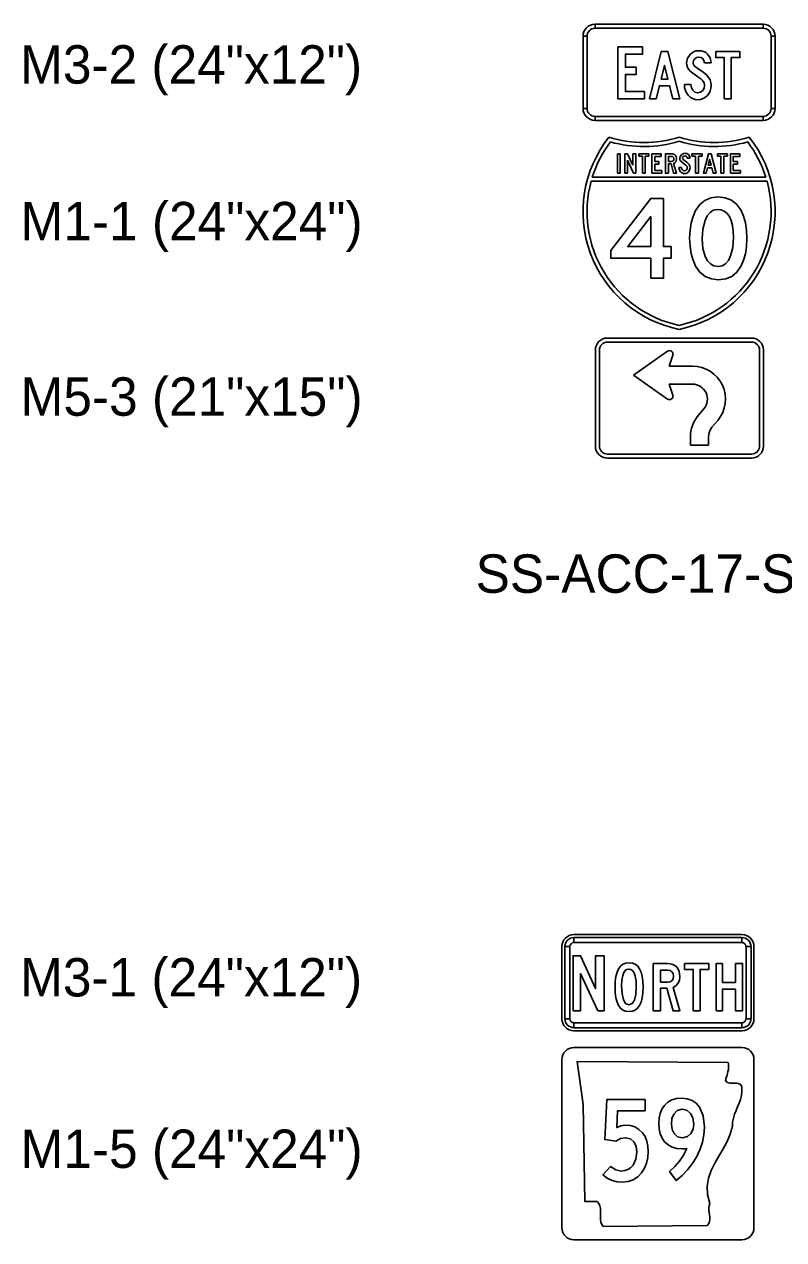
# Model space of a CAD drawing. Extents: x 620856.8 to 620948.6, y 415598.8 to 415658.2.
# Drawn here: x 620857.63 to 620865.53, y 415643.04 to 415655.69 of the extents above; entities that cross this region are included whole.
import ezdxf

# ---------------------------------------------------------------- set-up
doc = ezdxf.new("R2010")
doc.units = 0
doc.layers.add('SIGNS', color=7, linetype='Continuous')

msp = doc.modelspace()

# ---------------------------------------------------------------- linework, layer by layer
at = {"layer": 'SIGNS'}
for p, q in [((620863.57, 415655.647), (620863.57, 415655.689)), ((620865.32, 415655.689), (620865.32, 415655.647)), ((620863.445, 415655.564), (620863.487, 415655.564)), ((620865.403, 415655.564), (620865.445, 415655.564)), ((620863.487, 415654.814), (620863.445, 415654.814)), ((620865.445, 415654.814), (620865.403, 415654.814)), ((620863.57, 415654.689), (620863.57, 415654.73)), ((620865.32, 415654.73), (620865.32, 415654.689)), ((620863.833, 415654.342), (620863.804, 415654.342)), ((620863.804, 415654.342), (620863.804, 415654.138)), ((620863.833, 415654.138), (620863.833, 415654.342)), ((620863.907, 415654.342), (620863.879, 415654.342)), ((620863.879, 415654.342), (620863.879, 415654.138)), ((620863.964, 415654.221), (620863.907, 415654.342)), ((620863.907, 415654.138), (620863.907, 415654.276)), ((620863.907, 415654.276), (620863.972, 415654.138)), ((620863.995, 415654.342), (620863.964, 415654.342)), ((620863.964, 415654.342), (620863.964, 415654.221)), ((620863.995, 415654.138), (620863.995, 415654.342)), ((620864.13, 415654.342), (620864.025, 415654.342)), ((620864.025, 415654.342), (620864.025, 415654.317)), ((620864.025, 415654.317), (620864.063, 415654.317)), ((620864.063, 415654.317), (620864.063, 415654.138)), ((620864.092, 415654.138), (620864.092, 415654.317)), ((620864.092, 415654.317), (620864.13, 415654.317)), ((620864.13, 415654.317), (620864.13, 415654.342)), ((620864.258, 415654.342), (620864.161, 415654.342)), ((620864.161, 415654.342), (620864.161, 415654.138)), ((620864.191, 415654.262), (620864.191, 415654.314)), ((620864.191, 415654.314), (620864.258, 415654.314)), ((620864.258, 415654.314), (620864.258, 415654.342)), ((620864.457, 415654.313), (620864.453, 415654.294)), ((620864.453, 415654.294), (620864.454, 415654.283)), ((620864.454, 415654.283), (620864.457, 415654.274)), ((620864.469, 415654.331), (620864.457, 415654.313)), ((620864.457, 415654.274), (620864.462, 415654.265)), ((620864.477, 415654.338), (620864.469, 415654.331)), ((620864.486, 415654.342), (620864.477, 415654.338)), ((620864.482, 415654.294), (620864.484, 415654.304)), ((620864.483, 415654.288), (620864.482, 415654.294)), ((620864.486, 415654.282), (620864.483, 415654.288)), ((620864.484, 415654.304), (620864.489, 415654.311)), ((620864.495, 415654.345), (620864.486, 415654.342)), ((620864.502, 415654.27), (620864.486, 415654.282)), ((620864.489, 415654.311), (620864.497, 415654.316)), ((620864.506, 415654.346), (620864.495, 415654.345)), ((620864.497, 415654.316), (620864.506, 415654.318)), ((620864.526, 415654.254), (620864.502, 415654.27)), ((620864.517, 415654.345), (620864.506, 415654.346)), ((620864.506, 415654.318), (620864.517, 415654.316)), ((620864.527, 415654.343), (620864.517, 415654.345)), ((620864.517, 415654.316), (620864.524, 415654.312)), ((620864.524, 415654.312), (620864.528, 415654.305)), ((620864.536, 415654.338), (620864.527, 415654.343)), ((620864.528, 415654.305), (620864.531, 415654.294)), ((620864.531, 415654.294), (620864.559, 415654.294)), ((620864.544, 415654.332), (620864.536, 415654.338)), ((620864.555, 415654.315), (620864.544, 415654.332)), ((620864.559, 415654.294), (620864.555, 415654.315)), ((620864.685, 415654.342), (620864.579, 415654.342)), ((620864.579, 415654.342), (620864.579, 415654.317)), ((620864.579, 415654.317), (620864.617, 415654.317)), ((620864.617, 415654.317), (620864.617, 415654.138)), ((620864.646, 415654.138), (620864.646, 415654.317)), ((620864.646, 415654.317), (620864.685, 415654.317)), ((620864.685, 415654.317), (620864.685, 415654.342)), ((620864.949, 415654.342), (620864.844, 415654.342)), ((620864.844, 415654.342), (620864.844, 415654.317)), ((620864.844, 415654.317), (620864.881, 415654.317)), ((620864.881, 415654.317), (620864.881, 415654.138)), ((620864.911, 415654.138), (620864.911, 415654.317)), ((620864.911, 415654.317), (620864.949, 415654.317)), ((620864.949, 415654.317), (620864.949, 415654.342)), ((620865.077, 415654.342), (620864.979, 415654.342)), ((620864.979, 415654.342), (620864.979, 415654.138)), ((620865.009, 415654.262), (620865.009, 415654.314)), ((620865.009, 415654.314), (620865.077, 415654.314)), ((620865.077, 415654.314), (620865.077, 415654.342)), ((620864.233, 415654.262), (620864.191, 415654.262)), ((620864.191, 415654.166), (620864.191, 415654.234)), ((620864.191, 415654.234), (620864.233, 415654.234)), ((620864.266, 415654.166), (620864.191, 415654.166)), ((620864.233, 415654.234), (620864.233, 415654.262)), ((620864.266, 415654.138), (620864.266, 415654.166)), ((620864.472, 415654.199), (620864.444, 415654.199)), ((620864.444, 415654.199), (620864.444, 415654.198)), ((620864.444, 415654.198), (620864.445, 415654.185)), ((620864.445, 415654.185), (620864.448, 415654.174)), ((620864.448, 415654.174), (620864.453, 415654.163)), ((620864.453, 415654.163), (620864.46, 415654.153)), ((620864.46, 415654.153), (620864.469, 415654.145)), ((620864.462, 415654.265), (620864.469, 415654.257)), ((620864.469, 415654.257), (620864.502, 415654.234)), ((620864.469, 415654.145), (620864.479, 415654.139)), ((620864.474, 415654.186), (620864.472, 415654.199)), ((620864.48, 415654.175), (620864.474, 415654.186)), ((620864.489, 415654.167), (620864.48, 415654.175)), ((620864.502, 415654.164), (620864.489, 415654.167)), ((620864.502, 415654.234), (620864.514, 415654.224)), ((620864.514, 415654.166), (620864.502, 415654.164)), ((620864.514, 415654.224), (620864.522, 415654.217)), ((620864.523, 415654.174), (620864.514, 415654.166)), ((620864.522, 415654.217), (620864.529, 415654.207)), ((620864.529, 415654.184), (620864.523, 415654.174)), ((620864.525, 415654.139), (620864.535, 415654.145)), ((620864.541, 415654.24), (620864.526, 415654.254)), ((620864.529, 415654.207), (620864.531, 415654.196)), ((620864.531, 415654.196), (620864.529, 415654.184)), ((620864.535, 415654.145), (620864.544, 415654.153)), ((620864.549, 415654.23), (620864.541, 415654.24)), ((620864.544, 415654.153), (620864.551, 415654.162)), ((620864.555, 415654.22), (620864.549, 415654.23)), ((620864.551, 415654.162), (620864.555, 415654.173)), ((620864.558, 415654.208), (620864.555, 415654.22)), ((620864.555, 415654.173), (620864.558, 415654.184)), ((620864.559, 415654.196), (620864.558, 415654.208)), ((620864.558, 415654.184), (620864.559, 415654.196)), ((620865.052, 415654.262), (620865.009, 415654.262)), ((620865.009, 415654.166), (620865.009, 415654.234)), ((620865.009, 415654.234), (620865.052, 415654.234)), ((620865.085, 415654.166), (620865.009, 415654.166)), ((620865.052, 415654.234), (620865.052, 415654.262)), ((620865.085, 415654.138), (620865.085, 415654.166)), ((620865.349, 415654.096), (620863.541, 415654.096)), ((620863.804, 415654.138), (620863.833, 415654.138)), ((620863.879, 415654.138), (620863.907, 415654.138)), ((620863.972, 415654.138), (620863.995, 415654.138)), ((620864.063, 415654.138), (620864.092, 415654.138)), ((620864.161, 415654.138), (620864.266, 415654.138)), ((620864.479, 415654.139), (620864.49, 415654.135)), ((620864.49, 415654.135), (620864.502, 415654.134)), ((620864.502, 415654.134), (620864.514, 415654.135)), ((620864.514, 415654.135), (620864.525, 415654.139)), ((620864.617, 415654.138), (620864.646, 415654.138)), ((620864.881, 415654.138), (620864.911, 415654.138)), ((620864.979, 415654.138), (620865.085, 415654.138)), ((620863.699, 415652.423), (620865.199, 415652.423)), ((620865.199, 415652.381), (620863.699, 415652.381)), ((620865.199, 415652.423), (620865.199, 415652.423)), ((620863.574, 415651.298), (620863.574, 415652.298)), ((620863.616, 415652.298), (620863.616, 415651.298)), ((620864.325, 415652.287), (620863.97, 415652.037)), ((620864.342, 415652.131), (620864.379, 415652.245)), ((620865.282, 415651.298), (620865.282, 415652.298)), ((620865.324, 415652.298), (620865.324, 415651.298)), ((620864.584, 415652.131), (620864.342, 415652.131)), ((620863.97, 415652.037), (620864.325, 415651.788)), ((620864.379, 415651.83), (620864.342, 415651.944)), ((620864.342, 415651.944), (620864.584, 415651.944)), ((620864.704, 415651.687), (620864.644, 415651.615)), ((620864.787, 415651.494), (620864.848, 415651.566)), ((620864.563, 415651.394), (620864.563, 415651.308)), ((620864.751, 415651.308), (620864.751, 415651.394)), ((620864.563, 415651.308), (620864.751, 415651.308)), ((620863.699, 415651.214), (620865.199, 415651.214)), ((620865.199, 415651.173), (620863.699, 415651.173)), ((620863.699, 415651.173), (620863.699, 415651.173)), ((620865.1, 415646.213), (620863.35, 415646.213)), ((620863.35, 415646.13), (620863.35, 415646.182)), ((620865.1, 415646.182), (620865.1, 415646.13)), ((620863.225, 415646.088), (620863.225, 415645.338)), ((620863.256, 415646.088), (620863.309, 415646.088)), ((620865.142, 415646.088), (620865.194, 415646.088)), ((620865.225, 415645.338), (620865.225, 415646.088)), ((620863.309, 415645.338), (620863.256, 415645.338)), ((620863.35, 415645.244), (620863.35, 415645.296)), ((620865.1, 415645.296), (620865.1, 415645.244)), ((620865.194, 415645.338), (620865.142, 415645.338)), ((620863.35, 415645.213), (620865.1, 415645.213)), ((620865.1, 415645.037), (620863.35, 415645.037)), ((620863.225, 415644.912), (620863.225, 415643.162)), ((620865.225, 415643.162), (620865.225, 415644.912)), ((620863.225, 415643.162), (620863.225, 415643.162)), ((620863.35, 415643.037), (620865.1, 415643.037))]:
    msp.add_line(p, q, dxfattribs=at)
for points in [[(620865.32, 415655.689), (620863.57, 415655.689), (620863.57, 415655.647), (620865.32, 415655.647), (620865.32, 415655.689), (620865.32, 415655.689)], [(620863.445, 415655.564), (620863.445, 415654.814), (620863.487, 415654.814), (620863.487, 415655.564), (620863.445, 415655.564), (620863.445, 415655.564)], [(620865.445, 415654.814), (620865.445, 415655.564), (620865.403, 415655.564), (620865.403, 415654.814), (620865.445, 415654.814), (620865.445, 415654.814)], [(620864.086, 415654.988), (620863.887, 415654.988), (620863.887, 415655.167), (620864, 415655.167), (620864, 415655.242), (620863.887, 415655.242), (620863.887, 415655.379), (620864.065, 415655.379), (620864.065, 415655.453), (620863.809, 415655.453), (620863.809, 415654.914), (620864.086, 415654.914)], [(620864.501, 415655.061), (620864.501, 415655.057), (620864.503, 415655.027), (620864.511, 415654.999), (620864.523, 415654.974), (620864.539, 415654.951), (620864.561, 415654.93), (620864.585, 415654.916), (620864.611, 415654.907), (620864.64, 415654.904), (620864.669, 415654.907), (620864.696, 415654.915), (620864.72, 415654.929), (620864.741, 415654.949), (620864.757, 415654.972), (620864.769, 415654.997), (620864.776, 415655.024), (620864.778, 415655.054), (620864.775, 415655.082), (620864.767, 415655.109), (620864.753, 415655.135), (620864.734, 415655.159), (620864.697, 415655.191), (620864.64, 415655.23), (620864.603, 415655.258), (620864.595, 415655.272), (620864.592, 415655.289), (620864.596, 415655.311), (620864.609, 415655.329), (620864.628, 415655.342), (620864.651, 415655.346), (620864.675, 415655.342), (620864.693, 415655.33), (620864.703, 415655.313), (620864.71, 415655.289), (620864.778, 415655.289), (620864.767, 415655.339), (620864.741, 415655.378), (620864.722, 415655.394), (620864.701, 415655.405), (620864.676, 415655.411), (620864.649, 415655.414), (620864.624, 415655.411), (620864.601, 415655.404), (620864.58, 415655.392), (620864.561, 415655.376), (620864.533, 415655.335), (620864.524, 415655.287), (620864.526, 415655.262), (620864.533, 415655.24), (620864.545, 415655.219), (620864.561, 415655.2), (620864.641, 415655.143), (620864.67, 415655.12), (620864.689, 415655.104), (620864.705, 415655.079), (620864.71, 415655.053), (620864.706, 415655.024), (620864.692, 415654.999), (620864.669, 415654.981), (620864.64, 415654.975), (620864.61, 415654.982), (620864.587, 415655.002), (620864.573, 415655.029), (620864.569, 415655.061)], [(620864.916, 415654.914), (620864.987, 415654.914), (620864.987, 415655.342), (620865.079, 415655.342), (620865.079, 415655.404), (620864.826, 415655.404), (620864.826, 415655.342), (620864.916, 415655.342)], [(620863.57, 415654.689), (620865.32, 415654.689), (620865.32, 415654.73), (620863.57, 415654.73), (620863.57, 415654.689), (620863.57, 415654.689)], [(620865.1, 415646.182), (620863.35, 415646.182), (620863.35, 415646.13), (620865.1, 415646.13), (620865.1, 415646.182), (620865.1, 415646.182)], [(620863.256, 415646.088), (620863.256, 415645.338), (620863.309, 415645.338), (620863.309, 415646.088), (620863.256, 415646.088), (620863.256, 415646.088)], [(620865.194, 415645.338), (620865.194, 415646.088), (620865.142, 415646.088), (620865.142, 415645.338), (620865.194, 415645.338), (620865.194, 415645.338)], [(620863.341, 415645.421), (620863.419, 415645.421), (620863.419, 415645.808), (620863.6, 415645.421), (620863.664, 415645.421), (620863.664, 415645.993), (620863.576, 415645.993), (620863.576, 415645.652), (620863.419, 415645.993), (620863.341, 415645.993)], [(620864.592, 415645.421), (620864.664, 415645.421), (620864.664, 415645.85), (620864.755, 415645.85), (620864.755, 415645.912), (620864.503, 415645.912), (620864.503, 415645.85), (620864.592, 415645.85)], [(620864.83, 415645.421), (620864.897, 415645.421), (620864.897, 415645.646), (620865.032, 415645.646), (620865.032, 415645.421), (620865.107, 415645.421), (620865.107, 415645.912), (620865.032, 415645.912), (620865.032, 415645.715), (620864.897, 415645.715), (620864.897, 415645.912), (620864.83, 415645.912)], [(620863.35, 415645.244), (620865.1, 415645.244), (620865.1, 415645.296), (620863.35, 415645.296), (620863.35, 415645.244), (620863.35, 415645.244)], [(620864.955, 415644.883), (620864.96, 415644.864), (620864.961, 415644.844), (620864.961, 415644.825), (620864.958, 415644.806), (620864.954, 415644.787), (620864.95, 415644.768), (620864.944, 415644.749), (620864.938, 415644.731), (620864.933, 415644.713), (620864.928, 415644.694), (620864.942, 415644.678), (620864.959, 415644.669), (620864.979, 415644.665), (620865.001, 415644.665), (620865.022, 415644.665), (620865.043, 415644.666), (620865.062, 415644.663), (620865.078, 415644.657), (620865.091, 415644.645), (620865.099, 415644.625), (620865.1, 415644.579), (620865.094, 415644.537), (620865.084, 415644.496), (620865.069, 415644.458), (620865.054, 415644.42), (620865.038, 415644.382), (620865.023, 415644.343), (620865.011, 415644.304), (620865.002, 415644.262), (620865, 415644.218), (620864.978, 415644.136), (620864.944, 415644.058), (620864.904, 415643.982), (620864.86, 415643.907), (620864.816, 415643.833), (620864.779, 415643.757), (620864.751, 415643.678), (620864.736, 415643.596), (620864.74, 415643.508), (620864.765, 415643.415), (620864.758, 415643.391), (620864.755, 415643.368), (620864.756, 415643.344), (620864.759, 415643.319), (620864.762, 415643.296), (620864.765, 415643.272), (620864.765, 415643.249), (620864.762, 415643.227), (620864.754, 415643.206), (620864.738, 415643.186), (620863.655, 415643.176), (620863.64, 415643.196), (620863.631, 415643.22), (620863.628, 415643.246), (620863.627, 415643.275), (620863.628, 415643.304), (620863.628, 415643.334), (620863.626, 415643.363), (620863.621, 415643.39), (620863.61, 415643.414), (620863.591, 415643.434), (620863.465, 415643.434), (620863.447, 415644.446), (620863.383, 415644.893), (620864.955, 415644.883), (620864.955, 415644.883)], [(620863.65, 415643.711), (620863.698, 415643.678), (620863.748, 415643.655), (620863.8, 415643.641), (620863.855, 415643.637), (620863.914, 415643.643), (620863.967, 415643.661), (620864.014, 415643.691), (620864.055, 415643.734), (620864.086, 415643.782), (620864.107, 415643.834), (620864.121, 415643.892), (620864.125, 415643.955), (620864.121, 415644.012), (620864.11, 415644.064), (620864.091, 415644.111), (620864.063, 415644.151), (620864.027, 415644.186), (620863.984, 415644.211), (620863.935, 415644.226), (620863.881, 415644.231), (620863.84, 415644.224), (620863.796, 415644.204), (620863.805, 415644.379), (620864.092, 415644.379), (620864.092, 415644.495), (620863.692, 415644.495), (620863.671, 415644.079), (620863.788, 415644.064), (620863.836, 415644.09), (620863.889, 415644.099), (620863.941, 415644.087), (620863.979, 415644.052), (620863.999, 415644.006), (620864.006, 415643.949), (620863.996, 415643.874), (620863.966, 415643.813), (620863.941, 415643.786), (620863.913, 415643.767), (620863.879, 415643.756), (620863.842, 415643.752), (620863.785, 415643.764), (620863.731, 415643.799)]]:
    msp.add_lwpolyline(points, close=True, dxfattribs=at)
for points in [[(620864.136, 415654.914), (620864.208, 415654.914), (620864.241, 415655.049), (620864.347, 415655.049), (620864.381, 415654.914), (620864.453, 415654.914), (620864.329, 415655.404), (620864.26, 415655.404), (620864.136, 415654.914)], [(620864.258, 415655.118), (620864.293, 415655.261), (620864.329, 415655.118), (620864.258, 415655.118)], [(620863.714, 415654.513), (620863.714, 415654.513)], [(620863.73, 415654.465), (620863.73, 415654.465)], [(620864.445, 415654.471), (620864.445, 415654.471)], [(620865.16, 415654.465), (620865.16, 415654.465)], [(620865.176, 415654.513), (620865.176, 415654.513)], [(620864.334, 415654.138), (620864.334, 415654.235), (620864.362, 415654.235), (620864.388, 415654.138), (620864.418, 415654.138), (620864.388, 415654.239), (620864.401, 415654.246), (620864.41, 415654.257), (620864.416, 415654.27), (620864.418, 415654.285), (620864.417, 415654.297), (620864.414, 415654.308), (620864.41, 415654.318), (620864.404, 415654.326), (620864.396, 415654.333), (620864.387, 415654.338), (620864.376, 415654.341), (620864.363, 415654.342), (620864.302, 415654.342), (620864.302, 415654.138), (620864.334, 415654.138)], [(620864.334, 415654.262), (620864.334, 415654.314), (620864.364, 415654.314), (620864.375, 415654.313), (620864.383, 415654.307), (620864.389, 415654.299), (620864.39, 415654.288), (620864.389, 415654.277), (620864.384, 415654.269), (620864.376, 415654.264), (620864.365, 415654.262), (620864.334, 415654.262)], [(620864.728, 415654.138), (620864.742, 415654.194), (620864.786, 415654.194), (620864.8, 415654.138), (620864.83, 415654.138), (620864.779, 415654.342), (620864.75, 415654.342), (620864.698, 415654.138), (620864.728, 415654.138)], [(620864.749, 415654.223), (620864.763, 415654.283), (620864.779, 415654.223), (620864.749, 415654.223)], [(620863.529, 415654.055), (620864.072, 415654.055), (620864.599, 415654.055), (620865.361, 415654.055)], [(620864.849, 415653.892), (620864.776, 415653.883), (620864.714, 415653.856), (620864.661, 415653.812), (620864.617, 415653.75), (620864.59, 415653.689), (620864.571, 415653.621), (620864.559, 415653.546), (620864.555, 415653.464), (620864.559, 415653.379), (620864.571, 415653.301), (620864.59, 415653.232), (620864.617, 415653.171), (620864.661, 415653.109), (620864.716, 415653.064), (620864.781, 415653.038), (620864.856, 415653.029), (620864.931, 415653.038), (620864.994, 415653.065), (620865.048, 415653.11), (620865.091, 415653.173), (620865.117, 415653.232), (620865.135, 415653.3), (620865.146, 415653.376), (620865.15, 415653.459), (620865.146, 415653.546), (620865.135, 415653.623), (620865.116, 415653.692), (620865.09, 415653.751), (620865.046, 415653.813), (620864.992, 415653.857), (620864.926, 415653.883), (620864.849, 415653.892)], [(620864.15, 415653.045), (620864.282, 415653.045), (620864.282, 415653.254), (620864.362, 415653.254), (620864.362, 415653.375), (620864.282, 415653.375), (620864.282, 415653.876), (620864.15, 415653.876), (620863.734, 415653.333), (620863.734, 415653.254), (620864.15, 415653.254), (620864.15, 415653.045)], [(620865.011, 415653.468), (620865.004, 415653.365), (620864.982, 415653.279), (620864.959, 415653.23), (620864.929, 415653.195), (620864.893, 415653.175), (620864.851, 415653.168), (620864.808, 415653.174), (620864.772, 415653.194), (620864.741, 415653.226), (620864.717, 415653.271), (620864.693, 415653.356), (620864.685, 415653.456), (620864.693, 415653.556), (620864.715, 415653.645), (620864.738, 415653.695), (620864.767, 415653.731), (620864.801, 415653.753), (620864.842, 415653.76), (620864.881, 415653.756), (620864.916, 415653.742), (620864.945, 415653.719), (620864.969, 415653.687), (620864.987, 415653.646), (620865, 415653.596), (620865.008, 415653.536), (620865.011, 415653.468)], [(620864.15, 415653.375), (620863.91, 415653.375), (620864.15, 415653.688), (620864.15, 415653.375)], [(620864.445, 415652.555), (620864.445, 415652.555)], [(620864.445, 415652.513), (620864.445, 415652.513)], [(620863.699, 415652.423), (620863.699, 415652.423)], [(620863.574, 415652.298), (620863.574, 415652.298)], [(620865.324, 415651.298), (620865.324, 415651.298)], [(620865.199, 415651.173), (620865.199, 415651.173)], [(620864.07, 415645.667), (620864.068, 415645.727), (620864.061, 415645.778), (620864.05, 415645.822), (620864.034, 415645.858), (620864.014, 415645.885), (620863.989, 415645.905), (620863.959, 415645.917), (620863.926, 415645.921), (620863.891, 415645.917), (620863.861, 415645.905), (620863.836, 415645.885), (620863.815, 415645.858), (620863.799, 415645.822), (620863.788, 415645.778), (620863.781, 415645.727), (620863.779, 415645.667), (620863.781, 415645.607), (620863.788, 415645.555), (620863.799, 415645.511), (620863.815, 415645.476), (620863.835, 415645.447), (620863.86, 415645.428), (620863.889, 415645.416), (620863.923, 415645.412), (620863.957, 415645.416), (620863.987, 415645.428), (620864.013, 415645.447), (620864.033, 415645.476), (620864.05, 415645.511), (620864.061, 415645.555), (620864.068, 415645.607), (620864.07, 415645.667)], [(620864, 415645.67), (620863.995, 415645.588), (620863.981, 415645.53), (620863.957, 415645.495), (620863.923, 415645.483), (620863.889, 415645.495), (620863.865, 415645.533), (620863.851, 415645.595), (620863.846, 415645.682), (620863.849, 415645.74), (620863.858, 415645.788), (620863.869, 415645.817), (620863.884, 415645.839), (620863.902, 415645.851), (620863.923, 415645.855), (620863.944, 415645.851), (620863.962, 415645.837), (620863.977, 415645.814), (620863.988, 415645.781), (620863.997, 415645.73), (620864, 415645.67)], [(620864.177, 415645.421), (620864.253, 415645.421), (620864.253, 415645.655), (620864.319, 415645.655), (620864.383, 415645.421), (620864.453, 415645.421), (620864.382, 415645.663), (620864.413, 415645.68), (620864.436, 415645.707), (620864.449, 415645.739), (620864.453, 415645.774), (620864.451, 415645.804), (620864.445, 415645.83), (620864.435, 415645.853), (620864.42, 415645.873), (620864.401, 415645.89), (620864.379, 415645.902), (620864.353, 415645.909), (620864.323, 415645.912), (620864.177, 415645.912), (620864.177, 415645.421)], [(620864.253, 415645.719), (620864.253, 415645.844), (620864.325, 415645.844), (620864.351, 415645.84), (620864.371, 415645.827), (620864.384, 415645.807), (620864.388, 415645.782), (620864.384, 415645.754), (620864.373, 415645.735), (620864.354, 415645.723), (620864.328, 415645.719), (620864.253, 415645.719)], [(620863.35, 415645.037), (620863.35, 415645.037)], [(620865.1, 415645.037), (620865.1, 415645.037)], [(620863.225, 415644.912), (620863.225, 415644.912)], [(620864.346, 415643.748), (620864.414, 415643.653), (620864.477, 415643.706), (620864.533, 415643.764), (620864.582, 415643.828), (620864.626, 415643.898), (620864.662, 415643.974), (620864.688, 415644.052), (620864.704, 415644.129), (620864.709, 415644.208), (620864.696, 415644.327), (620864.659, 415644.418), (620864.624, 415644.459), (620864.581, 415644.488), (620864.53, 415644.505), (620864.471, 415644.511), (620864.417, 415644.507), (620864.369, 415644.492), (620864.328, 415644.468), (620864.293, 415644.434), (620864.267, 415644.395), (620864.248, 415644.351), (620864.237, 415644.302), (620864.234, 415644.248), (620864.237, 415644.191), (620864.249, 415644.14), (620864.268, 415644.095), (620864.295, 415644.057), (620864.331, 415644.024), (620864.373, 415644.001), (620864.423, 415643.987), (620864.48, 415643.982), (620864.504, 415643.984), (620864.527, 415643.986), (620864.525, 415643.986), (620864.491, 415643.917), (620864.45, 415643.854), (620864.402, 415643.798), (620864.346, 415643.748)], [(620864.597, 415644.245), (620864.59, 415644.188), (620864.569, 415644.143), (620864.532, 415644.11), (620864.48, 415644.099), (620864.43, 415644.109), (620864.393, 415644.142), (620864.372, 415644.185), (620864.366, 415644.24), (620864.371, 415644.298), (620864.389, 415644.345), (620864.425, 415644.383), (620864.476, 415644.396), (620864.527, 415644.384), (620864.567, 415644.349), (620864.589, 415644.301), (620864.597, 415644.245)], [(620863.35, 415643.037), (620863.35, 415643.037)], [(620865.1, 415643.037), (620865.1, 415643.037)]]:
    msp.add_lwpolyline(points, dxfattribs=at)
for centre, radius, start, end in [((620863.57, 415655.564), 0.125, 90.0002, 179.9998), ((620865.32, 415655.564), 0.125, 0, 90.0002), ((620863.57, 415655.564), 0.0833, 90.0002, 179.9998), ((620865.32, 415655.564), 0.0833, 0, 90.0002), ((620863.57, 415654.814), 0.125, 179.9998, 270.0001), ((620863.57, 415654.814), 0.0833, 179.9998, 270.0001), ((620865.32, 415654.814), 0.125, 270.0001, 0.0003), ((620865.32, 415654.814), 0.0833, 270.0001, 0.0003), ((620864.695, 415653.738), 1.25, 141.669, 258.463), ((620864.695, 415653.737), 1.208, 142.9959, 162.6952), ((620864.08, 415655.709), 1.25, 253.009, 286.9909), ((620864.077, 415655.709), 1.292, 254.4391, 286.5746), ((620864.195, 415653.738), 1.25, 281.5371, 38.3311), ((620864.81, 415655.709), 1.25, 253.0091, 286.9911), ((620864.814, 415655.709), 1.292, 253.4255, 285.561), ((620864.195, 415653.737), 1.208, 17.3047, 37.0041), ((620864.695, 415653.737), 1.208, 164.7534, 258.0704), ((620864.195, 415653.737), 1.208, 281.9296, 15.2467), ((620864.195, 415653.737), 1.208, 281.9296126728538, 281.9296393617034), ((620864.695, 415653.737), 1.208, 258.0704, 258.0705), ((620863.699, 415652.298), 0.125, 90.0002, 179.9998), ((620863.699, 415652.298), 0.0833, 90.0002, 179.9998), ((620865.199, 415652.298), 0.125, 0, 90), ((620865.199, 415652.298), 0.0833, 0, 90.0002), ((620864.345, 415652.256), 0.0365, 341.5654, 122.8665), ((620864.584, 415651.787), 0.344, 320.0027, 90.0056), ((620864.584, 415651.787), 0.156, 319.9975, 89.9999), ((620864.345, 415651.818), 0.0365, 237.1341, 18.4346), ((620864.907, 415651.394), 0.344, 139.9518, 179.954), ((620864.907, 415651.394), 0.156, 140.0372, 180.04), ((620863.699, 415651.298), 0.125, 179.9998, 270), ((620863.699, 415651.298), 0.0833, 179.9998, 270.0001), ((620865.199, 415651.298), 0.125, 270.0001, 360), ((620865.199, 415651.298), 0.0833, 270.0001, 0.0003), ((620863.35, 415646.088), 0.125, 90.0002, 179.9998), ((620863.35, 415646.088), 0.0937, 90.0002, 179.9998), ((620865.1, 415646.088), 0.125, 360, 90.0002), ((620865.1, 415646.088), 0.0937, 360, 90.0002), ((620863.35, 415646.088), 0.0417, 90.0002, 179.9998), ((620865.1, 415646.088), 0.0417, 360, 90.0002), ((620863.35, 415645.338), 0.125, 179.9998, 270.0001), ((620863.35, 415645.338), 0.0937, 179.9998, 270.0001), ((620863.35, 415645.338), 0.0417, 179.9998, 270.0001), ((620865.1, 415645.338), 0.125, 270.0001, 0.0003), ((620865.1, 415645.338), 0.0937, 270.0001, 0.0003), ((620865.1, 415645.338), 0.0417, 270.0001, 0.0003), ((620863.35, 415644.912), 0.125, 90.0002, 179.9998), ((620865.1, 415644.912), 0.125, 360, 90), ((620863.35, 415643.162), 0.125, 180, 270), ((620865.1, 415643.162), 0.125, 270.0001, 0.0003)]:
    msp.add_arc(centre, radius, start, end, dxfattribs=at)

# ---------------------------------------------------------------- texts
for s, p in [('M3-2 (24"x12")', (620857.585, 415655.071)), ('M1-1 (24"x24")', (620857.59, 415653.44)), ('M5-3 (21"x15")', (620857.59, 415651.614)), ('SS-ACC-17-STA105+25EB', (620862.327, 415649.771)), ('M3-1 (24"x12")', (620857.585, 415645.569)), ('M1-5 (24"x24")', (620857.59, 415643.784))]:
    msp.add_text(s, height=0.4, rotation=0, dxfattribs=at).set_placement(p)

doc.saveas('drawing.dxf')
